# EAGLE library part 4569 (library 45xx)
Programmable dual 4 bit binary/BCD down COUNTER
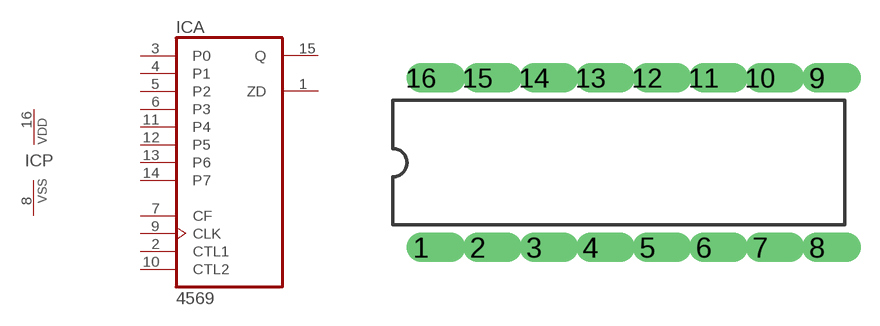
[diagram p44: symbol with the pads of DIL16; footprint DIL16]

Designator prefix IC; gates A=4569 P=PWRN

## 4569N  [DIL16]
1  A:ZD  out
2  A:CTL1  in
3  A:P0  in
4  A:P1  in
5  A:P2  in
6  A:P3  in
7  A:CF  in
8  P:VSS  pwr
9  A:CLK  in
10  A:CTL2  in
11  A:P4  in
12  A:P5  in
13  A:P6  in
14  A:P7  in
15  A:Q  out
16  P:VDD  pwr

## Footprint DIL16 (pad centres in mm)
Dual In Line
drill 0.813 offset: 1 -8.89,-3.81; 2 -6.35,-3.81; 3 -3.81,-3.81; 4 -1.27,-3.81; 5 1.27,-3.81; 6 3.81,-3.81; 7 6.35,-3.81; 8 8.89,-3.81; 9 8.89,3.81; 10 6.35,3.81; 11 3.81,3.81; 12 1.27,3.81; 13 -1.27,3.81; 14 -3.81,3.81; 15 -6.35,3.81; 16 -8.89,3.81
